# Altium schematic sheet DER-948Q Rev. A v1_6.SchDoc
size A3; Organization: Power Integrations Switzerland GmbH; PageSetup: Record=PageOptions¦CenterHorizontal=True¦CenterVertical=True¦PrintScale=1.00¦XCorrection=1.00¦YCorrection=1.00¦PrintKind=0¦BorderSize=5000000¦LeftOffset=0¦BottomOffset=0¦Orientation=2¦PaperLength=4200¦PaperWidth=2970¦Scale=100¦PaperSource=7¦PrintQuality=600¦MediaType=1¦DitherType=10¦PaperKind=A3¦PrintScaleMode=1
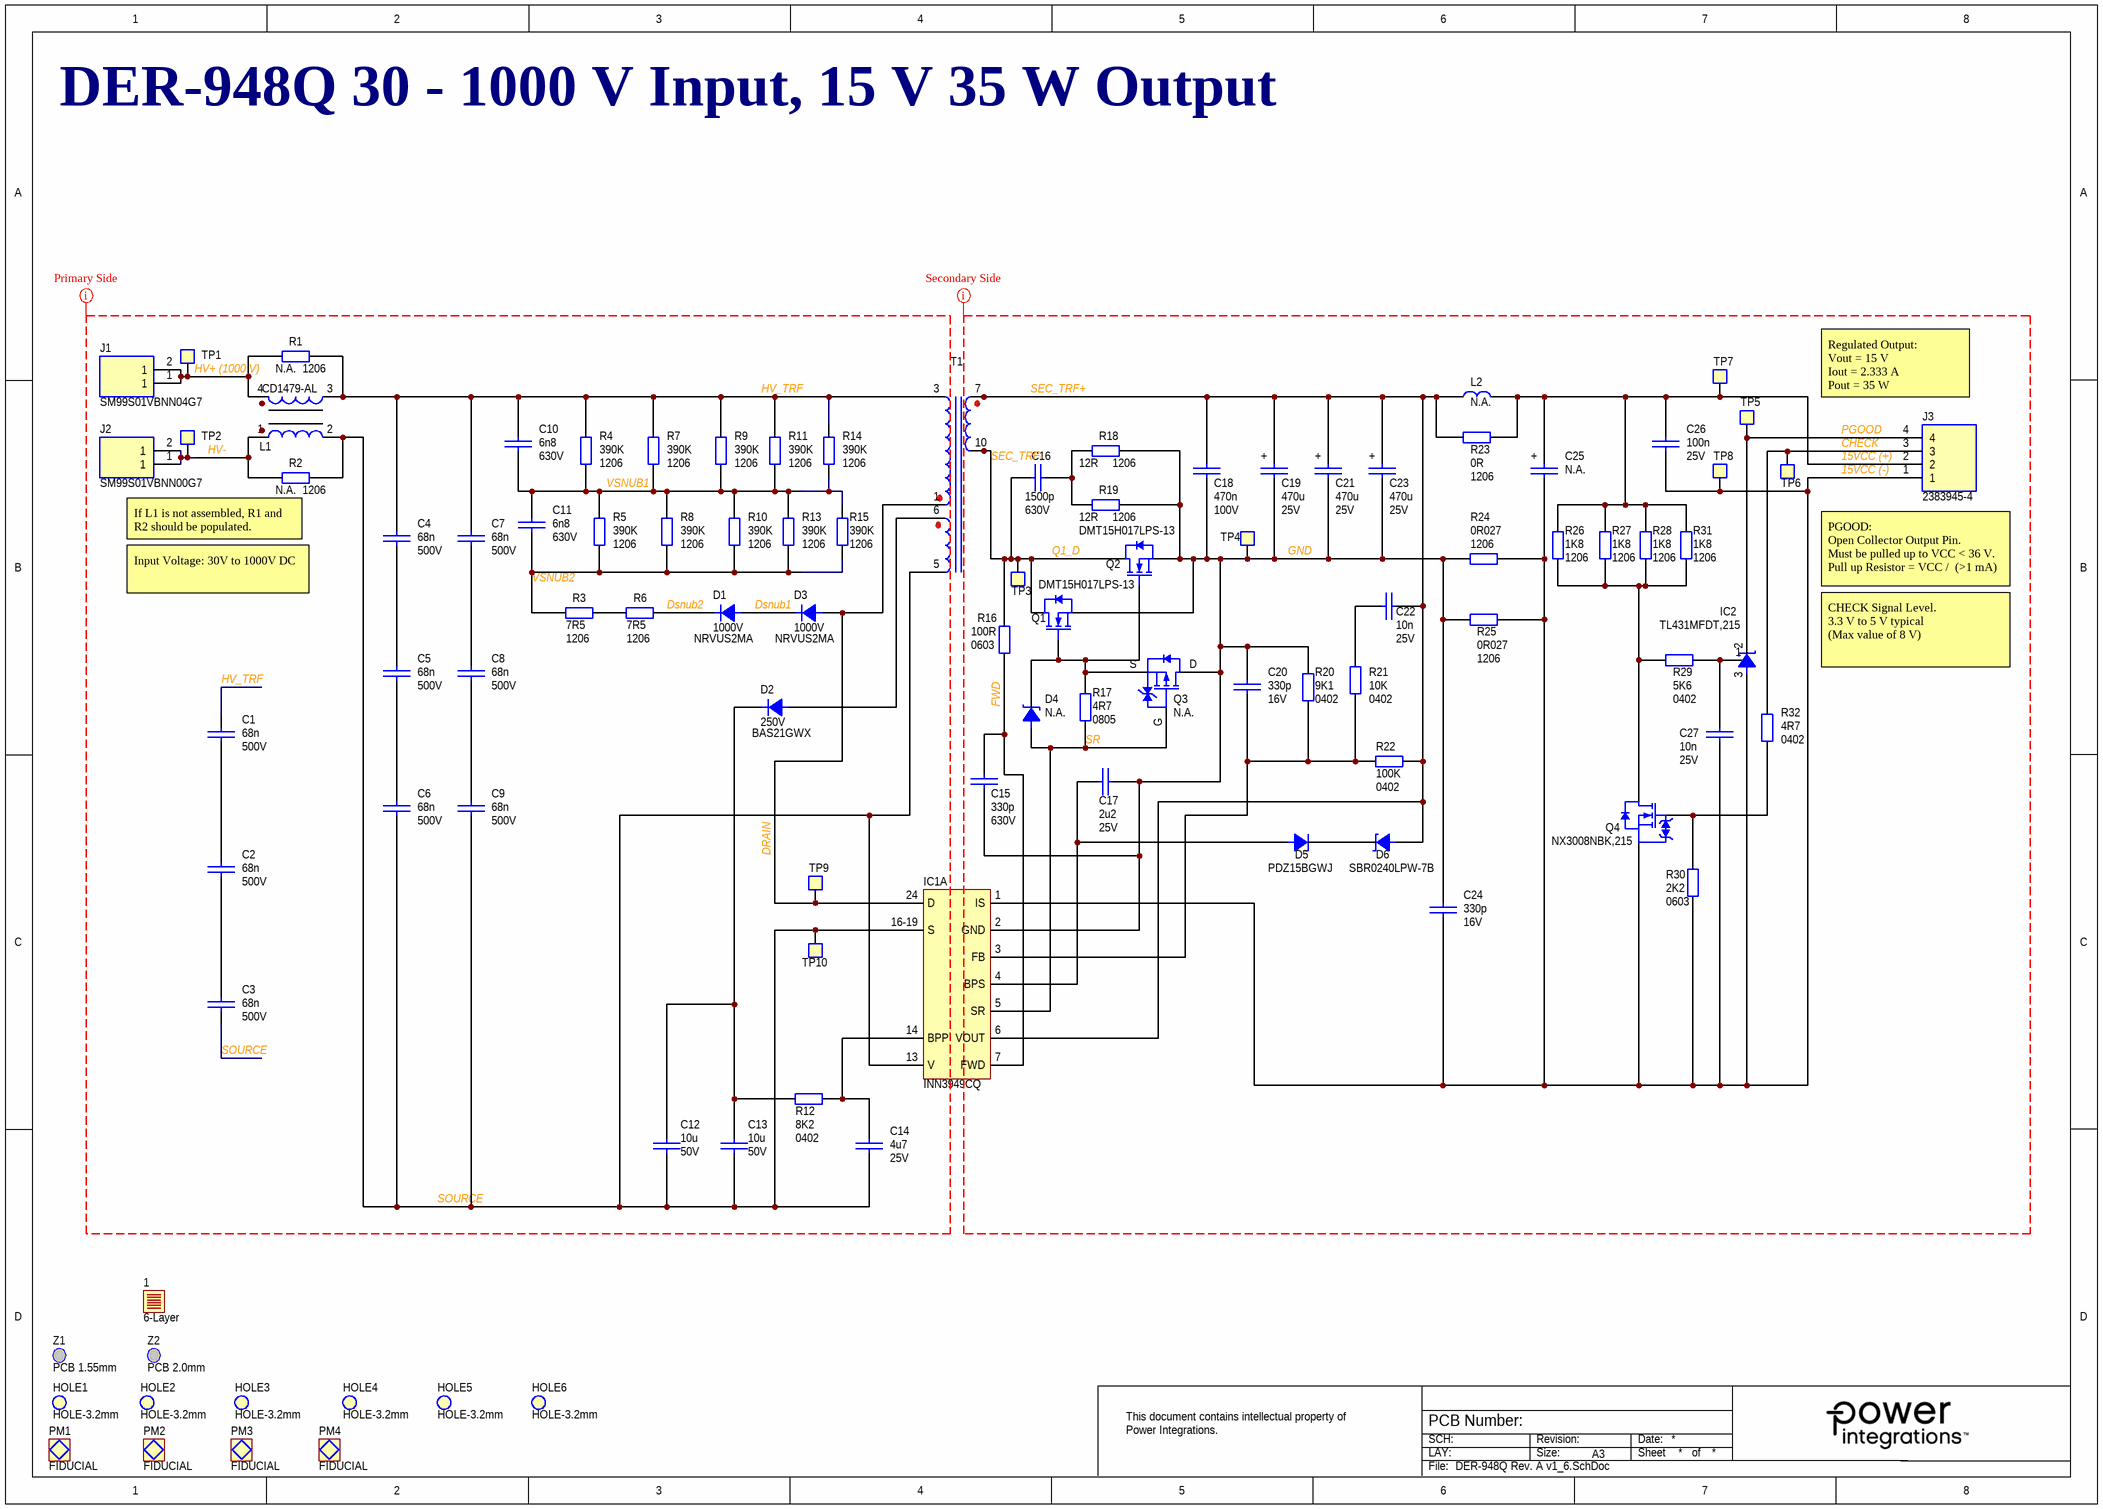
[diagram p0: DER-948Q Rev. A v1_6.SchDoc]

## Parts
1  6-Layer  [PCB_6-LAYER]  (no BOM)
C1  Voltage: 500V  [CT_1206_C_RS]  (hidden comment: 68n)
C2  Voltage: 500V  [CT_1206_C_RS]  (hidden comment: 68n)
C3  Voltage: 500V  [CT_1206_C_RS]  (hidden comment: 68n)
C4  Voltage: 500V  [CT_1206_C_RS]  (hidden comment: 68n)
C5  Voltage: 500V  [CT_1206_C_RS]  (hidden comment: 68n)
C6  Voltage: 500V  [CT_1206_C_RS]  (hidden comment: 68n)
C7  Voltage: 500V  [CT_1206_C_RS]  (hidden comment: 68n)
C8  Voltage: 500V  [CT_1206_C_RS]  (hidden comment: 68n)
C9  Voltage: 500V  [CT_1206_C_RS]  (hidden comment: 68n)
C10  Voltage: 630V  [CT_1206_C_RS]  (hidden comment: 6n8)
C11  Voltage: 630V  [CT_1206_C_RS]  (hidden comment: 6n8)
C12  Voltage: 50V  [CT_1206_C_RS]  (hidden comment: 10u)
C13  Voltage: 50V  [CT_1206_C_RS]  (hidden comment: 10u)
C14  Voltage: 25V  [CT_0805_C_RS]  (hidden comment: 4u7)
C15  330p  Voltage: 630V  [ATV_1206_C_RS]
C16  Voltage: 630V  [ATV_1206_C_RS]  (hidden comment: 1500p)
C17  Voltage: 25V  [CT_0805_C_RS]  (hidden comment: 2u2)
C18  Voltage: 100V  [ATV_1206_C_RS]  (hidden comment: 470n)
C19  Voltage: 25V  [CAPAE10x12p5L_B40900]  (hidden comment: 470u)
C20  Voltage: 16V  [ATV_0402_C]  (hidden comment: 330p)
C21  470u  Voltage: 25V  [CAPAE10x12p5L_B40900]
C22  10n  Voltage: 25V  [ATV_0402_C]
C23  Voltage: 25V  [CAPAE10x12p5L_B40900]  (hidden comment: 470u)
C24  330p  Voltage: 16V  [ATV_0402_C]
C25  N.A.  [CAPAE8x10L_GYC]
C26  Voltage: 25V  [CT_0603_C_RS]  (hidden comment: 100n)
C27  10n  Voltage: 25V  [ATV_0402_C]
D1  NRVUS2MA  Reverse Voltage: 1000V  [CT_DIODE_SMA_RS]
D2  Reverse Voltage: 250V  [CT_SOD123_RS]  (hidden comment: BAS21GWX)
D3  NRVUS2MA  Reverse Voltage: 1000V  [CT_DIODE_SMA_RS]
D4  N.A.  [CT_SOD323_RS]
D5  PDZ15BGWJ  [CT_SOD123_RS]
D6  SBR0240LPW-7B  [CT_DIODE_X1-DFN1006-2_RS]
HOLE1  HOLE-3.2mm  [PCB_HOLE-3.2]  (no BOM)
HOLE2  HOLE-3.2mm  [PCB_HOLE-3.2]  (no BOM)
HOLE3  HOLE-3.2mm  [PCB_HOLE-3.2]  (no BOM)
HOLE4  HOLE-3.2mm  [PCB_HOLE-3.2]  (no BOM)
HOLE5  HOLE-3.2mm  [PCB_HOLE-3.2]  (no BOM)
HOLE6  HOLE-3.2mm  [PCB_HOLE-3.2]  (no BOM)
IC1  INN3949CQ  [ATV_InSOP-24D]  (part A of 2)
IC2  TL431MFDT,215  [CT_SOT23_RS]
J1  SM99S01VBNN04G7  [ATV_METZ_SM99S01VB]
J2  SM99S01VBNN00G7  [ATV_METZ_SM99S01VB]
J3  2383945-4  [ATV_TE_2383945-4]
L1  Type Designation 1: CD1479-AL  [ATV_CD1479-ALD]  (hidden comment: 590uH)
L2  N.A.  [CT_IND_1008_RS]
PM1  FIDUCIAL  [PCB_FIDUCIAL]  (no BOM)
PM2  FIDUCIAL  [PCB_FIDUCIAL]  (no BOM)
PM3  FIDUCIAL  [PCB_FIDUCIAL]  (no BOM)
PM4  FIDUCIAL  [PCB_FIDUCIAL]  (no BOM)
Q1  DMT15H017LPS-13  [CT_PowerDI5060-8_RS]
Q2  DMT15H017LPS-13  [CT_PowerDI5060-8_RS]
Q3  N.A.  [ATV_SOT323_FET_P]
Q4  NX3008NBK,215  [ATV_SOT23_FET]
R1  N.A.  Package: 1206  [ATV_1206_R_RS]
R2  N.A.  Package: 1206  [ATV_1206_R_RS]
R3  7R5  Package: 1206  [ATV_1206_R_RS]
R4  390K  Package: 1206  [ATV_1206_R_RS]
R5  390K  Package: 1206  [ATV_1206_R_RS]
R6  7R5  Package: 1206  [ATV_1206_R_RS]
R7  390K  Package: 1206  [ATV_1206_R_RS]
R8  390K  Package: 1206  [ATV_1206_R_RS]
R9  390K  Package: 1206  [ATV_1206_R_RS]
R10  390K  Package: 1206  [ATV_1206_R_RS]
R11  390K  Package: 1206  [ATV_1206_R_RS]
R12  Package: 0402  [ATV_0402_R]  (hidden comment: 8K2)
R13  390K  Package: 1206  [ATV_1206_R_RS]
R14  390K  Package: 1206  [ATV_1206_R_RS]
R15  390K  Package: 1206  [ATV_1206_R_RS]
R16  Package: 0603  [CT_0603_R_RS]  (hidden comment: 100R)
R17  Package: 0805  [CT_0805_R_RS]  (hidden comment: 4R7)
R18  Package: 1206  [ATV_1206_R_RS]  (hidden comment: 12R)
R19  Package: 1206  [ATV_1206_R_RS]  (hidden comment: 12R)
R20  Package: 0402  [ATV_0402_R]  (hidden comment: 9K1)
R21  10K  Package: 0402  [ATV_0402_R]
R22  Package: 0402  [ATV_0402_R]  (hidden comment: 100K)
R23  Package: 1206  [CT_1206_R_RS]  (hidden comment: 0R)
R24  0R027  Package: 1206  [CT_1206_R_RS]
R25  0R027  Package: 1206  [CT_1206_R_RS]
R26  1K8  Package: 1206  [CT_1206_R_RS]
R27  1K8  Package: 1206  [CT_1206_R_RS]
R28  1K8  Package: 1206  [CT_1206_R_RS]
R29  5K6  Package: 0402  [ATV_0402_R]
R30  2K2  Package: 0603  [CT_0603_R_RS]
R31  1K8  Package: 1206  [CT_1206_R_RS]
R32  4R7  Package: 0402  [ATV_0402_R]
T1  TRF_EQ-30-1-L  [ATV_TRF_EQ-30-1-L]  (value not drawn)
TP1  ICT-100SP-BL  [ICT-100SP-BL-25MIL]  (value not drawn)  (no BOM)
TP2  ICT-100SP-BL  [ICT-100SP-BL-25MIL]  (value not drawn)  (no BOM)
TP3  ICT-100SP-BL  [ICT-100SP-BL-25MIL]  (value not drawn)  (no BOM)
TP4  ICT-100SP-BL  [ICT-100SP-BL-25MIL]  (value not drawn)  (no BOM)
TP5  ICT-100SP-BL  [ICT-100SP-BL-25MIL]  (value not drawn)  (no BOM)
TP6  ICT-100SP-BL  [ICT-100SP-BL-25MIL]  (value not drawn)  (no BOM)
TP7  ICT-100SP-BL  [ICT-100SP-BL-25MIL]  (value not drawn)  (no BOM)
TP8  ICT-100SP-BL  [ICT-100SP-BL-25MIL]  (value not drawn)  (no BOM)
TP9  ICT-100SP-BL  [ICT-100SP-BL-25MIL]  (value not drawn)  (no BOM)
TP10  ICT-100SP-BL  [ICT-100SP-BL-25MIL]  (value not drawn)  (no BOM)
Z1  PCB 1.55mm  (mechanical)
Z2  PCB 2.0mm  (mechanical)

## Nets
15VCC (+): C25.1 C26.1 J3.2 L2.2 R23.2 R26.1 R27.1 R28.1 R31.1 TP7.1
15VCC (-): C24.2 C25.2 C26.2 C27.1 IC1.1(IS) IC2.3(A) J3.1 Q4.S(SOURCE) R24.2 R25.2 R30.2 TP8.1
CHECK: J3.3 R32.1 TP6.1
DRAIN: D3.A IC1.24(D) T1.1 TP9.1
Dsnub1: D1.A D3.K
Dsnub2: D1.K R6.2
FWD: C15.2 IC1.7(FWD) R16.2
GND: C15.1 C17.2 C18.2 C19.2 C20.1 C21.2 C23.2 C24.1 IC1.2(GND) Q1.S(SOURCE) Q2.S(SOURCE) Q3.D(Drain) R18.2 R19.2 R20.1 R24.1 R25.1 TP4.1
HV+ (1000 V): J1.1 J1.2(1) L1.4 R1.1 TP1.1
HV-: J2.1 J2.2(1) L1.1 R2.1 TP2.1
HV_TRF: C1.1 C4.1 C7.1 C10.1 L1.3 R1.2 R4.1 R7.1 R9.1 R11.1 R14.1 T1.3
PGOOD: IC2.2(K) J3.4 TP5.1
Q1_D: C16.1 Q1.D(DRAIN) Q2.D(DRAIN) R16.1 T1.9 T1.10(pin7,_pin8) TP3.1  [also labelled SEC_TRF-]
SEC_TRF+: C18.1 C19.1 C21.1 C22.1 C23.1 D6.A IC1.6(VOUT) L2.1 R22.2 R23.1 T1.7 T1.8
SOURCE: C3.2 C6.2 C9.2 C12.2 C13.2 C14.2 IC1.13(V) IC1.16-19(S) L1.2 R2.2 T1.5 TP10.1
SR: D4.A IC1.5(SR) Q3.G(GATE) R17.2
VSNUB1: C10.2 C11.1 R4.2 R5.1 R7.2 R8.1 R9.2 R10.1 R11.2 R13.1 R14.2 R15.1
VSNUB2: C11.2 R3.1 R5.2 R8.2 R10.2 R13.2 R15.2
NetC1_2: C1.2 C2.1
NetC2_2: C2.2 C3.1
NetC4_2: C4.2 C5.1
NetC5_2: C5.2 C6.1
NetC7_2: C7.2 C8.1
NetC8_2: C8.2 C9.1
NetC12_1: C12.1 C13.1 D2.K R12.1
NetC14_1: C14.1 IC1.14(BPP) R12.2
NetC16_2: C16.2 R18.1 R19.1
NetC17_1: C17.1 D5.A IC1.4(BPS)
NetC20_2: C20.2 IC1.3(FB) R20.2 R21.2 R22.1
NetC22_2: C22.2 R21.1
NetC27_2: C27.2 IC2.1(Ref) R29.2
NetD2_A: D2.A T1.6
NetD4_K: D4.K Q1.G(GATE) Q2.G(GATE) Q3.S(SOURCE) R17.1
NetD5_K: D5.K D6.K
NetQ4_D: Q4.D(DRAIN) R26.2 R27.2 R28.2 R29.1 R31.2
NetQ4_G: Q4.G(GATE) R30.1 R32.2
NetR3_2: R3.2 R6.1

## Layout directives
net class Secondary Side 1: 15VCC (+), 15VCC (-), CHECK, FWD, GND, PGOOD, Q1_D, SEC_TRF+, SEC_TRF-, SR
net class Primary Side: DRAIN, Dsnub1, Dsnub2, HV+ (1000 V), HV-, HV_TRF, SOURCE, VSNUB1, VSNUB2

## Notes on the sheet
- DER-948Q 30 - 1000 V Input, 15 V 35 W Output
- (near L2) If L2 is not assembled, R23 should be populated.
- For Rsn's R4, R5, R7, R8, R9, R10, R11, R13, R14 and R15 use land pattern (which will serve as Cooling Area) with minimum dimensions of 1.8mmx2.5mm for each pad.
- (near J3) Regulated Output:
  Vout = 15 V
  Iout = 2.333 A
  Pout = 35 W
- If L1 is not assembled, R1 and R2 should be populated.
- Input Voltage: 30V to 1000V DC
- (near J3) PGOOD:
  Open Collector Output Pin.
  Must be pulled up to VCC < 36 V.
  Pull up Resistor = VCC /  (>1 mA)
- Cooling Cu area required for EACH SR FET is 1.02sq inch minimum (662mm2) total on top and bottom layers
- CHECK Signal Level.
  3.3 V to 5 V typical
  (Max value of 8 V)
- Cooling Cu area required for IC1 is 1sqinch minimum total on top and bottom layers

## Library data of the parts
1 = ATV-MISC-0011: Second Source: N; Release Status: active; Release Status Sign: GW
C1-C9 = ATV-CAP-0230: Part Description: Ceramic Chip Capacitor; Manufacturer 1: KEMET; Parameters: X7R/500V/10%; Dielectric: X7R; Tolerance: 10%; Second Source: Y; AEC-Q: AEC-Q200; Target Usage: for product use; Confidence Level: 0%; Release Status: inactive; Release Status Sign: RAA; Type Designation 1: C1206C683KCRACAUTO
C10 C11 = ATV-CAP-0258: Part Description: Ceramic Chip Capacitor; Manufacturer 1: TDK; Parameters: C0G/630V/5%; Dielectric: C0G; Tolerance: 5%; Second Source: Y; AEC-Q: AEC-Q200; Target Usage: for product use; Confidence Level: 0%; Release Status: inactive; Release Status Sign: RAA; Type Designation 1: CGA5H4C0G2J682J115AE
C12 C13 = ATV-CAP-0226: Part Description: Ceramic Chip Capacitor; Manufacturer 1: TDK; Parameters: X7R/50V/10%; Dielectric: X7R; Tolerance: 10%; Second Source: N; AEC-Q: AEC-Q200; Target Usage: for product use; Confidence Level: 0%; Release Status: inactive; Release Status Sign: GW; Type Designation 1: CGA5L1X7R1H106K160AE
C14 = ATV-CAP-0244: Part Description: Ceramic Chip Capacitor; Manufacturer 1: TDK; Parameters: X7R/25V/20%; Dielectric: X7R; Tolerance: 20%; Second Source: Y; AEC-Q: AEC-Q200; Target Usage: for product use; Confidence Level: 0%; Release Status: inactive; Release Status Sign: RAA; Type Designation 1: CGA4J1X7R1E475M125AC
C15 = ATV-CAP-0233: Part Description: Ceramic Chip Capacitor; Manufacturer 1: TDK; Parameters: C0G/630V/5%; Dielectric: C0G; Tolerance: 5%; Second Source: Y; AEC-Q: AEC-Q200; Target Usage: for product use; Confidence Level: 0%; Release Status: inactive; Release Status Sign: RAA; Type Designation 1: CGA5C4C0G2J331J060AA
C16 = ATV-CAP-0299: Part Description: Ceramic Chip Capacitor; Manufacturer 1: TDK; Parameters: C0G/630V/5%; Dielectric: C0G; Tolerance: 5%; Second Source: Y; AEC-Q: AEC-Q200; Target Usage: for product use; Confidence Level: 0%; Release Status: inactive; Release Status Sign: RAA; Type Designation 1: CGA5H4C0G2J152J115AA
C17 = ATV-CAP-0248: Part Description: Ceramic Chip Capacitor; Manufacturer 1: KEMET; Parameters: X7R/25V/10%; Dielectric: X7R; Tolerance: 10%; Second Source: Y; AEC-Q: AEC-Q200; Target Usage: for product use; Confidence Level: 0%; Release Status: inactive; Release Status Sign: RAA; Type Designation 1: C0805C225K3RACAUTO
C18 = ATV-CAP-0249: Part Description: Ceramic Chip Capacitor; Manufacturer 1: Taiyo Yuden; Parameters: X7R/100V/10%; Dielectric: X7R; Tolerance: 10%; Second Source: Y; AEC-Q: AEC-Q200; Target Usage: for product use; Confidence Level: 0%; Release Status: inactive; Release Status Sign: RAA; Type Designation 1: HMK316B7474KLHT
C19 C23 = ATV-CAP-0250: Part Description: Polymer Aluminium Capacitor; Manufacturer 1: EPCOS / TDK; Parameters: AL/25V/20%; Tolerance: 20%; Second Source: Y; Target Usage: for product use; Confidence Level: 0%; Release Status: inactive; Release Status Sign: RAA; Dielectric: AL; Type Designation 1: B40900B5477M000
C20 C24 = ATV-CAP-0246: Part Description: Ceramic Chip Capacitor; Manufacturer 1: Vishay; Parameters: X7R/16V/10%; Dielectric: X7R; Tolerance: 10%; Second Source: Y; AEC-Q: AEC-Q200; Target Usage: for product use; Confidence Level: 0%; Release Status: inactive; Release Status Sign: RAA; Type Designation 1: VJ0402Y331KLJAJ32
C21 = ATV-CAP-0250: Part Description: Polymer Aluminium Capacitor; Manufacturer 1: EPCOS / TDK; Target Usage: for product use; Confidence Level: 0%; Release Status: inactive; Release Status Sign: RAA; Parameters: AL/25V/20%; Dielectric: AL; Tolerance: 20%; Second Source: Y; Type Designation 1: B40900B5477M000
C22 C27 = ATV-CAP-0065: Part Description: Ceramic Chip Capacitor; Manufacturer 1: TDK; Parameters: X7R/25V/10%; Dielectric: X7R; Tolerance: 10%; Second Source: N; AEC-Q: AEC-Q200; Target Usage: for product use; Confidence Level: 0%; Release Status: active; Release Status Sign: CH; Type Designation 1: CGA2B2X7R1E103K050BA
C25 = ATV-CAP-0298: Part Description: Polymer Aluminium Capacitor; Confidence Level: 0%; Release Status: inactive; Release Status Sign: RAA
C26 = ATV-CAP-0239: Part Description: Ceramic Chip Capacitor; Manufacturer 1: TDK; Parameters: X7R/25V/10%; Dielectric: X7R; Tolerance: 10%; Second Source: Y; AEC-Q: AEC-Q200; Target Usage: for product use; Confidence Level: 0%; Release Status: inactive; Release Status Sign: RAA; Type Designation 1: CGA3E2X7R1E104K080AA
D1 D3 = ATV-DIO-0035: Part Description: Rectifiers 1000V 1.5A High Efficiency Rectifier; Manufacturer 1: On Semi; Parameters: 1000V/1.5A; Forward Voltage: 1.7V @ If = 1.5A; Current: 1.5A; Target Usage: for product use; Confidence Level: 0%; Release Status: inactive; Release Status Sign: RAA; Second Source: N; AEC-Q: AEC-Q101
D2 = ATV-DIO-0036: Part Description: Diode Standard 200 V 225mA (DC) Surface Mount SOD-123; Manufacturer 1: Nexperia; Parameters: 200 V / 225mA; Forward Voltage: 1.25v @ If = 200mA; Current: 200mA; AEC-Q: AEC-Q101; Target Usage: for product use; Confidence Level: 0%; Release Status: inactive; Release Status Sign: RAA; Power: 250mW; Second Source: N
D4 = ATV-DIO-0066: Part Description: Diode Schottky; Confidence Level: 0%; Release Status: inactive; Release Status Sign: RAA
D5 = ATV-DIO-0048: Part Description: DIODE ZENER 15V 365MW SOD123; Manufacturer 1: Nexperia; Parameters: 15V / 365mW; AEC-Q: AEC-Q101; Target Usage: for product use; Confidence Level: 0%; Release Status: inactive; Release Status Sign: RAA; Forward Voltage: 0.9V @ 10mA; Current: 1.1mV @100mA; Power: 365mW; Tolerance: 2.13%; Second Source: N; Voltage: 15V
D6 = ATV-DIO-0038: Part Description: Diode Standard 40 V 200mA Surface Mount X1-DFN1006-2; Manufacturer 1: Diodes Incorporated; Parameters: 40 V / 200mA; Forward Voltage: 590mV @ If =200mA; Reverse Voltage: 40V; Current: 200mA; Target Usage: for product use; Confidence Level: 0%; Release Status: inactive; Release Status Sign: RAA; Second Source: N
HOLE1-HOLE6 = ATV-MISC-0013: Part Description: 3.2mm; Second Source: N; Confidence Level: 0%; Release Status: active; Release Status Sign: GW
IC1 = ATV-IC-0054: Manufacturer 1: Power Integrations; Part Description: InnoSwitch3; Target Usage: for product use; Confidence Level: 0%; Release Status: inactive; Release Status Sign: RAA; Parameters: 4.65V to 5.15V/Vmos=1700V; Supply Voltage: 4.65V to 5.15V; Other: Ilim=2.3A, Pout=60W; Second Source: N; AEC-Q: AEC-Q100
IC2 = ATV-IC-0048: Part Description: Voltage References 2.495 VIN ADJ Shunt; Manufacturer 1: Nexperia; Output Voltage: 2.4-36V; AEC-Q: AEC-Q101; Target Usage: for product use; Confidence Level: 0%; Release Status: active; Release Status Sign: RAA; Parameters: 2.4-36V / 100mA; Supply Voltage: 2.4v - 36V; Output Current: 100mA; Second Source: N; Type Designation 1: TL431MFDT,215 / TL431MFDT,215
J1 = ATV-MISC-0037: Part Description: TERM BLOCK 1POS SIDE ENTRY SMD; Manufacturer 1: METZ CONNECT USA Inc.; Parameters: RED; Second Source: N; Target Usage: for product use; Confidence Level: 0%; Release Status: inactive; Release Status Sign: RAA
J2 = ATV-MISC-0036: Part Description: TERM BLOCK 1POS SIDE ENTRY SMD; Manufacturer 1: METZ CONNECT USA Inc.; Parameters: BLACK; Second Source: N; Target Usage: for product use; Confidence Level: 0%; Release Status: inactive; Release Status Sign: RAA
J3 = ATV-MISC-0039: Part Description: TERMI-BLOK SMD MOUNT 180_4P_3.81; Manufacturer 1: TE Connectivity AMP Connectors; Second Source: N; Target Usage: for product use; Confidence Level: 0%; Release Status: inactive; Release Status Sign: RAA
L1 = ATV-IND-0018: Part Description: Input Common Mode Choke; Manufacturer 1: Coilcraft; Target Usage: for product use; Confidence Level: 0%; Release Status: inactive; Release Status Sign: RAA; Current: 4.2A; Resistor: 20mOhm; Second Source: N; AEC-Q: AEC-Q20
L2 = ATV-IND-0022: Part Description: Shielded Wirewound Inductor; Confidence Level: 0%; Release Status: inactive; Release Status Sign: RAA
PM1-PM4 = ATV-MISC-0007: Part Description: Mark; Second Source: N; Release Status: active; Release Status Sign: GW
Q1 Q2 = ATV-FET-0017: Part Description: N-Channel MOSFET; Manufacturer 1: Diodes; Target Usage: for product use; Confidence Level: 0%; Release Status: inactive; Release Status Sign: RAA; Parameters: 150 V 9.4A (Ta), 58A (Tc) 1.3W (Ta); Gates: 1; Polarisation: N; Voltage: 150V; Current: 9.4A; Power: 1.3W; Resistor: 17.5mOhm @ Vgs = 20V / Id = 9.4
Q3 = ATV-FET-0028: Part Description: P-Channel MOSFET; Confidence Level: 0%; Release Status: inactive; Release Status Sign: RAA; Gates: 1; Polarisation: P
Q4 = ATV-FET-0019: Part Description: N-Channel MOSFET; Manufacturer 1: Nexperia; AEC-Q: AEC-Q101; Target Usage: for product use; Confidence Level: 0%; Release Status: inactive; Release Status Sign: RAA; Parameters: 30 V 400mA (Tc) 350mW (Ta), 1.14W (Tc); Gates: 1; Polarisation: N; Voltage: 30V; Current: 400mA; Power: 1.14W; Resistor: 1.4Ohm @ 350mA, 4.5V
R1 R2 = ATV-RES-0818: Part Description: Thick Film Chip Resistor; Confidence Level: 0%; Release Status: inactive; Release Status Sign: RAA
R3 R6 = ATV-RES-0822: Part Description: Thick Film Chip Resistor; Manufacturer 1: ROHM Semiconductor; Power: 0.5W; Tolerance: 5%; AEC-Q: AEC-Q200; Target Usage: for product use; Confidence Level: 0%; Release Status: inactive; Release Status Sign: RAA; Parameters: 5%/0.5W/200V; Second Source: Y; Type Designation 1: ESR18EZPJ7R5
R4 R5 R7-R11 R13-R15 = ATV-RES-0823: Part Description: Thick Film Chip Resistor; Manufacturer 1: ROHM Semiconductor; Power: 0.5W; Tolerance: 5%; AEC-Q: AEC-Q200; Target Usage: for product use; Confidence Level: 0%; Release Status: inactive; Release Status Sign: RAA; Parameters: 5%/0.5W/200V; Second Source: Y; Type Designation 1: ESR18EZPJ394
R12 = ATV-RES-0752: Part Description: Thick Film Chip Resistor; Manufacturer 1: Bourns; Power: 0.063W; Tolerance: 5%; AEC-Q: AEC-Q200; Target Usage: for product use; Confidence Level: 0%; Release Status: inactive; Release Status Sign: RAA; Parameters: 5%/0.063W/50V; Voltage: 50V; Second Source: Y; Type Designation 1: CR0402AJW-822GLF
R16 = ATV-RES-0753: Part Description: Thick Film Chip Resistor; Manufacturer 1: Stackpole Electronics Inc; Power: 0.1W; Tolerance: 5%; AEC-Q: AEC-Q200; Target Usage: for product use; Confidence Level: 0%; Release Status: inactive; Release Status Sign: RAA; Parameters: 5%/0.1W; Second Source: Y; Type Designation 1: RMCF0603JT100R
R17 = ATV-RES-0740: Part Description: Thick Film Chip Resistor; Manufacturer 1: YAGEO; Power: 0.125W; Tolerance: 5%; AEC-Q: AEC-Q200; Target Usage: for product use; Confidence Level: 0%; Release Status: inactive; Release Status Sign: RAA; Parameters: 5%/0.125W/150V; Voltage: 150V; Second Source: Y; Type Designation 1: AC0805JR-074R7L
R18 R19 = ATV-RES-0824: Part Description: Thick Film Chip Resistor; Manufacturer 1: YAGEO; Power: 0.25W; Tolerance: 5%; AEC-Q: AEC-Q200; Target Usage: for product use; Confidence Level: 0%; Release Status: inactive; Release Status Sign: RAA; Parameters: 5%/0.25W/200V; Second Source: Y; Type Designation 1: AC1206JR-0712RL
R20 = ATV-RES-0757: Part Description: Thick Film Chip Resistor; Manufacturer 1: Panasonic; Power: 0.1W; Tolerance: 1%; AEC-Q: AEC-Q200; Target Usage: for product use; Confidence Level: 0%; Release Status: inactive; Release Status Sign: RAA; Parameters: 1%/0.1W/50V; Voltage: 50V; Second Source: Y; Type Designation 1: ERJ-2RKF9101X
R21 = ATV-RES-0743: Part Description: Thick Film Chip Resistor; Manufacturer 1: Panasonic; Tolerance: 5%; Power: 0.1W; AEC-Q: AEC-Q200; Target Usage: for product use; Confidence Level: 0%; Release Status: inactive; Release Status Sign: RAA; Parameters: 5%/0.1W/50V; Voltage: 50V; Second Source: Y; Type Designation 1: ERJ-U02J103X
R22 = ATV-RES-0756: Part Description: Thick Film Chip Resistor; Manufacturer 1: Stackpole Electronics Inc; Power: 0.063W; Tolerance: 1%; AEC-Q: AEC-Q200; Target Usage: for product use; Confidence Level: 0%; Release Status: inactive; Release Status Sign: RAA; Parameters: 1%/0.063W; Second Source: Y; Type Designation 1: RMCF0402FT100K
R23 = ATV-RES-0762: Part Description: Thick Film Chip Resistor; Manufacturer 1: YAGEO; Parameters: 1%/0.25W/200V; Tolerance: 1%; Power: 0.25W; Voltage: 200V; Second Source: Y; AEC-Q: AEC-Q200; Target Usage: for product use; Type Designation 1: AF1206JR-070RL; Confidence Level: 0%; Release Status: inactive; Release Status Sign: RAA
R24 R25 = ATV-RES-0778: Part Description: Current Sense Resistor; Manufacturer 1: Vishay; Power: 0.25W; Tolerance: 1%; AEC-Q: AEC-Q200; Target Usage: for product use; Confidence Level: 0%; Release Status: inactive; Release Status Sign: RAA; Parameters: 1%/0.25W; Second Source: Y; Type Designation 1: WSL1206R0270FEA
R26-R28 R31 = ATV-RES-0765: Part Description: Thick Film Chip Resistor; Manufacturer 1: Panasonic; Power: 0.25W; Tolerance: 5%; AEC-Q: AEC-Q200; Target Usage: for product use; Confidence Level: 0%; Release Status: inactive; Release Status Sign: RAA; Parameters: 5%/0.25W; Second Source: Y; Type Designation 1: ERJ-8GEYJ182V
R29 = ATV-RES-0825: Part Description: Thick Film Chip Resistor; Manufacturer 1: Panasonic; Power: 0.1W; Tolerance: 5%; AEC-Q: AEC-Q200; Target Usage: for product use; Confidence Level: 0%; Release Status: inactive; Release Status Sign: RAA; Parameters: 5%/0.1W/50V; Second Source: Y; Type Designation 1: ERJ-2GEJ562X
R30 = ATV-RES-0760: Part Description: Thick Film Chip Resistor; Manufacturer 1: YAGEO; Power: 0.1W; Tolerance: 5%; AEC-Q: AEC-Q200; Target Usage: for product use; Confidence Level: 0%; Release Status: inactive; Release Status Sign: RAA; Parameters: 5%/0.1W/75V; Voltage: 75V; Second Source: Y; Type Designation 1: AC0603JR-072K2L
R32 = ATV-RES-0745: Part Description: Thick Film Chip Resistor; Manufacturer 1: YAGEO; Power: 0.063W; Tolerance: 5%; AEC-Q: AEC-Q200; Target Usage: for product use; Confidence Level: 0%; Release Status: inactive; Release Status Sign: RAA; Parameters: 5%/0.063W/50V; Voltage: 50V; Second Source: Y; Type Designation 1: AC0402JR-074R7L
T1 = ATV-TRF-0022: Part Description: Selfmade Transformer on base ElQ30; Manufacturer 1: Power Integrations; Value: EIQ30-10P-SMD-35W; Parameters: Lp=278µH Llk=4.17µH P=35W; Supply Voltage: 30-1000V; Output Voltage: 15V; Second Source: N; Target Usage: for product use; Type Designation 1: ElQ30; Confidence Level: 0%; Release Status: inactive; Release Status Sign: RAA
TP1-TP10 = ATV-MISC-0025: Part Description: Spring Probes 2.54mm; Manufacturer 1: UWE electronic; Second Source: N; Confidence Level: 0%; Release Status: active; Release Status Sign: GW
Z1 = ATV-MISC-0005: Part Description: Printed Circuit Board; Parameters: PCB thickness 1.55mm; Second Source: N; Release Status: active; Release Status Sign: GW
Z2 = ATV-MISC-0001: Part Description: Printed Circuit Board; Parameters: PCB thickness 2.0mm; Second Source: N; Release Status: active; Release Status Sign: GW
